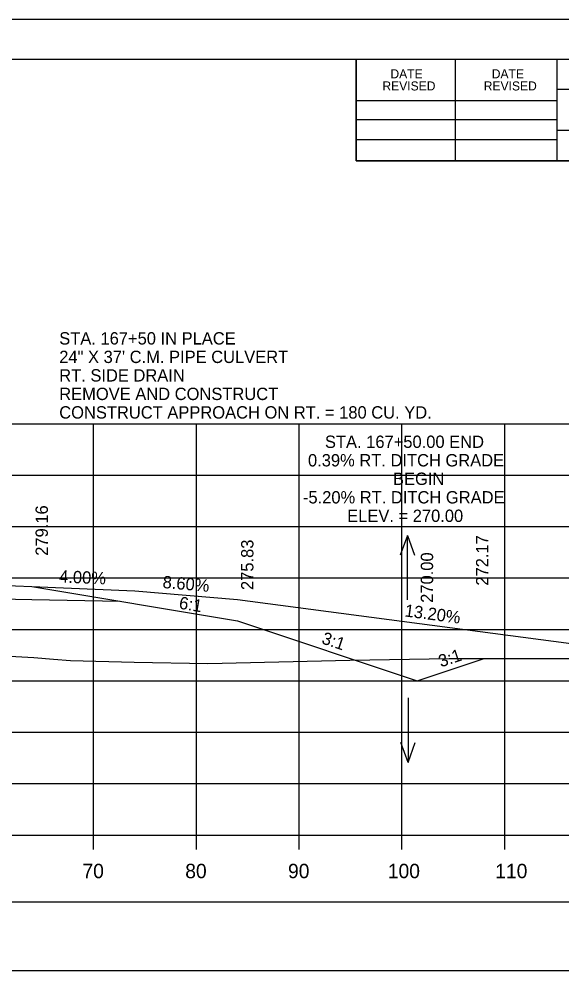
# Model space of a CAD drawing. Extents: x 285 to 4233, y -659 to 3710.
# Drawn here: x 1286.4 to 1339.2, y 1145.9 to 1238.9 of the extents above; entities that cross this region are included whole.
import ezdxf

# ---------------------------------------------------------------- set-up
doc = ezdxf.new("R2010")
doc.units = 0
for name, color, linetype in [('R_Alt Surface', 7, 'Continuous'), ('R_Axis', 7, 'Continuous'), ('R_Axis Annot', 7, 'Continuous'), ('R_Border', 7, 'Continuous'), ('R_Drive', 7, 'Continuous'), ('R_Exist Surface', 7, 'Continuous'), ('R_Fin Surface', 7, 'Continuous'), ('R_Grid', 7, 'Continuous'), ('R_No Plot', 7, 'Continuous'), ('R_Water Annot', 7, 'Continuous'), ('R_Xsect Elev', 7, 'Continuous'), ('R_Xsect Slope', 7, 'Continuous')]:
    doc.layers.add(name, color=color, linetype=linetype)

msp = doc.modelspace()

# ---------------------------------------------------------------- linework, layer by layer
at = {"layer": 'R_Alt Surface'}
msp.add_lwpolyline([(1238.304, 1182.839), (1247.677, 1183.026), (1253.676, 1183.146), (1253.676, 1183.146), (1279.676, 1182.626), (1287.676, 1182.466), (1296.245, 1182.295)], dxfattribs=at)
at = {"layer": 'R_Axis'}
for p, q in [((1073.677, 1159.563), (1373.677, 1159.563)), ((1293.677, 1158.163), (1293.677, 1159.563)), ((1303.677, 1158.163), (1303.677, 1159.563)), ((1313.677, 1158.163), (1313.677, 1159.563)), ((1323.677, 1158.163), (1323.677, 1159.563)), ((1333.677, 1158.163), (1333.677, 1159.563))]:
    msp.add_line(p, q, dxfattribs=at)
at = {"layer": 'R_Axis Annot'}
msp.add_lwpolyline([(1234.456, 1146.385), (1374.456, 1146.385), (1374.456, 1153.037), (1234.456, 1153.037)], close=True, dxfattribs=at)
at = {"layer": 'R_Border'}
for p, q in [((1065.677, 1235.023), (1381.857, 1235.023)), ((1319.217, 1225.143), (1319.217, 1235.023)), ((1328.897, 1225.143), (1328.897, 1235.023)), ((1338.757, 1235.023), (1338.757, 1225.143)), ((1381.857, 1232.083), (1338.757, 1232.083)), ((1319.217, 1231.003), (1338.757, 1231.003)), ((1319.217, 1229.143), (1338.757, 1229.143)), ((1381.857, 1228.083), (1338.757, 1228.083)), ((1319.217, 1227.203), (1338.757, 1227.203)), ((1381.857, 1225.143), (1319.217, 1225.143))]:
    msp.add_line(p, q, dxfattribs=at)
at = {"layer": 'R_Drive'}
for p, q in [((1287.677, 1183.723), (1297.677, 1183.323)), ((1297.677, 1183.323), (1307.677, 1182.463)), ((1307.677, 1182.463), (1345.024, 1177.533))]:
    msp.add_line(p, q, dxfattribs=at)
at = {"layer": 'R_Exist Surface'}
msp.add_lwpolyline([(1281.976, 1177.156), (1287.861, 1176.834), (1289.78, 1176.679), (1291.431, 1176.521), (1297.634, 1176.384), (1304.787, 1176.261), (1318.605, 1176.568), (1328.265, 1176.739), (1334.834, 1176.734), (1337.871, 1176.743), (1344.312, 1176.732), (1356.407, 1176.349), (1360.878, 1176.259), (1373.677, 1176.177)], dxfattribs=at)
at = {"layer": 'R_Fin Surface'}
msp.add_lwpolyline([(1208.977, 1175.624), (1223.677, 1180.523), (1247.677, 1184.323), (1253.677, 1184.563), (1277.677, 1184.083), (1279.677, 1184.043), (1287.677, 1183.723), (1307.677, 1180.39), (1325.157, 1174.563), (1331.676, 1176.737)], dxfattribs=at)
at = {"layer": 'R_Grid'}
for p, q in [((1073.677, 1199.563), (1373.677, 1199.563)), ((1293.677, 1159.563), (1293.677, 1199.563)), ((1303.677, 1159.563), (1303.677, 1199.563)), ((1313.677, 1159.563), (1313.677, 1199.563)), ((1323.677, 1159.563), (1323.677, 1199.563)), ((1333.677, 1159.563), (1333.677, 1199.563)), ((1073.677, 1194.563), (1373.677, 1194.563)), ((1073.677, 1189.563), (1373.677, 1189.563)), ((1073.677, 1184.563), (1373.677, 1184.563)), ((1073.677, 1179.563), (1373.677, 1179.563)), ((1073.677, 1174.563), (1373.677, 1174.563)), ((1073.677, 1169.563), (1373.677, 1169.563)), ((1073.677, 1164.563), (1373.677, 1164.563)), ((1073.677, 1159.563), (1373.677, 1159.563))]:
    msp.add_line(p, q, dxfattribs=at)
at = {"layer": 'R_No Plot'}
msp.add_line((1053.276, 1238.918), (1386.609, 1238.918), dxfattribs=at)
for points in [[(1053.269, 1238.918), (1386.609, 1238.918), (1386.609, 1025.58), (1053.269, 1025.58)], [(1299.597, 1235.023), (1319.217, 1235.023), (1319.217, 1225.143), (1335.329, 1225.143), (1358.528, 1225.143), (1358.649, 1196.987), (1381.857, 1196.987), (1381.857, 1029.563), (1065.677, 1029.563), (1065.677, 1235.023)]]:
    msp.add_lwpolyline(points, close=True, dxfattribs=at)
at = {"layer": 'R_Water Annot'}
for p, q in [((1324.206, 1188.711), (1323.506, 1186.788)), ((1324.206, 1182.427), (1324.206, 1188.711)), ((1324.206, 1188.711), (1324.906, 1186.788)), ((1324.274, 1172.914), (1324.274, 1166.63)), ((1324.274, 1166.63), (1323.574, 1168.553)), ((1324.274, 1166.63), (1324.974, 1168.553))]:
    msp.add_line(p, q, dxfattribs=at)

# ---------------------------------------------------------------- texts
at = {"layer": 'R_Axis Annot'}
for s, p in [('70', (1292.591, 1155.363)), ('80', (1302.591, 1155.363)), ('90', (1312.591, 1155.363)), ('100', (1322.304, 1155.363)), ('110', (1332.756, 1155.363))]:
    msp.add_text(s, height=1.4, dxfattribs=at).set_placement(p)
at = {"layer": 'R_Border'}
for s, p in [('DATE', (1322.554, 1233.16)), ('DATE', (1332.414, 1233.16)), ('REVISED', (1321.774, 1231.98)), ('REVISED', (1331.634, 1231.98))]:
    msp.add_text(s, height=0.8792, rotation=360, dxfattribs=at).set_placement(p)
at = {"layer": 'R_Water Annot'}
for s, p in [('STA. 167+50 IN PLACE', (1290.33, 1207.27)), ('24" X 37\' C.M. PIPE CULVERT ', (1290.33, 1205.47)), ('RT. SIDE DRAIN', (1290.33, 1203.67)), ('REMOVE AND CONSTRUCT', (1290.33, 1201.87)), ('CONSTRUCT APPROACH ON RT. = 180 CU. YD.', (1290.33, 1200.07))]:
    msp.add_text(s, height=1.2, dxfattribs=at).set_placement(p)
at = {"layer": 'R_Xsect Elev'}
for s, p in [('STA. 167+50.00 END', (1316.183, 1197.212)), ('0.39% RT. DITCH GRADE', (1314.534, 1195.412)), ('BEGIN', (1322.807, 1193.612)), ('-5.20% RT. DITCH GRADE', (1314.043, 1191.812)), ('ELEV. = 270.00', (1318.347, 1190.012))]:
    msp.add_text(s, height=1.2, dxfattribs=at).set_placement(p)
for s, rotation, p in [('279.16', 90, (1289.226, 1186.723)), ('272.17', 90, (1332.081, 1183.815)), ('275.83', 90, (1309.226, 1183.39)), ('270.00', 90, (1326.707, 1182.147)), ('4.00%', 357.70939, (1290.304, 1184.119)), ('8.60%', 355.08466, (1300.352, 1183.595)), ('13.20%', 352.48043, (1323.891, 1180.827))]:
    msp.add_text(s, height=1.2, rotation=rotation, dxfattribs=at).set_placement(p)
at = {"layer": 'R_Xsect Slope'}
for s, rotation, p in [('6:1', 350.53864, (1301.925, 1181.592)), ('3:1', 341.56478, (1315.786, 1178.214)), ('3:1', 18.43346, (1327.47, 1175.861))]:
    msp.add_text(s, height=1.2, rotation=rotation, dxfattribs=at).set_placement(p)

doc.saveas('drawing.dxf')
